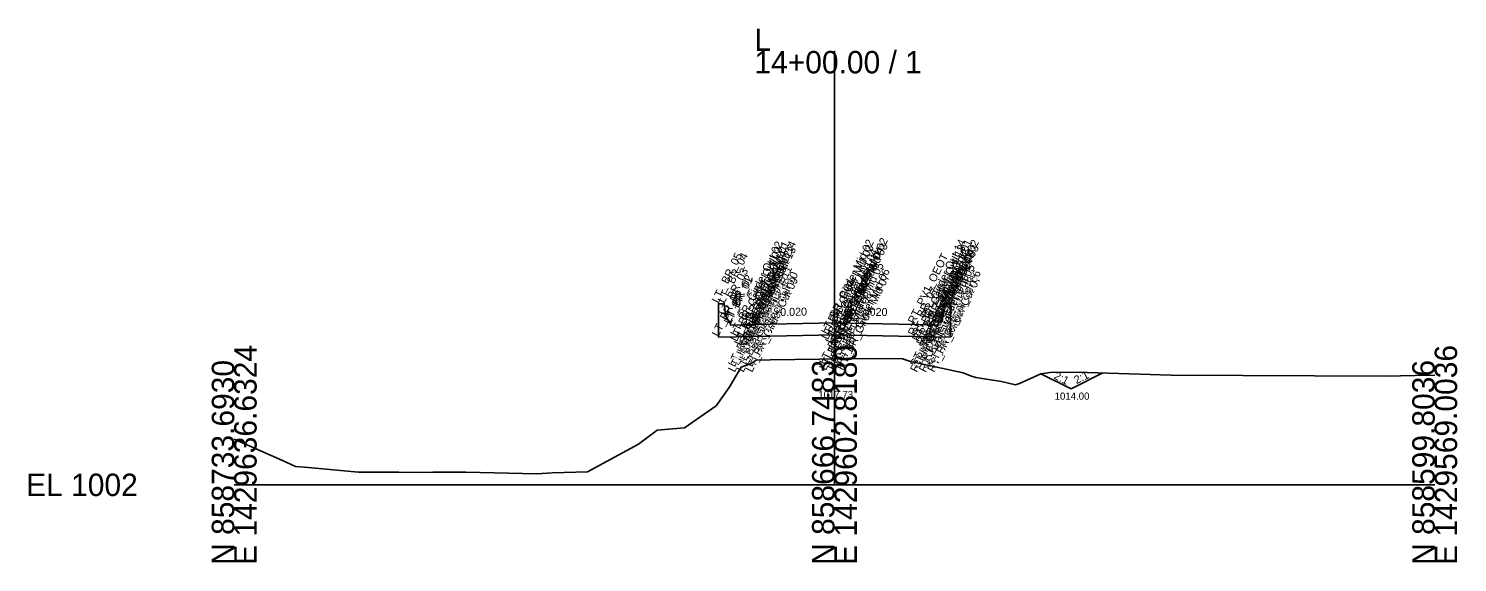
# Model space of a CAD drawing. Extents: x -26 to 153, y -10 to 13058.
# Drawn here: x -25.7 to 152.8, y 4990.3 to 5057 of the extents above; entities that cross this region are included whole.
import ezdxf

# ---------------------------------------------------------------- set-up
doc = ezdxf.new("R2010")
doc.units = 0
for name, color, linetype in [('Default', 7, 'Continuous'), ('Exist Cross Section Cell', 7, 'Continuous'), ('Exist XS Center Line Elevation Label', 7, 'Continuous'), ('Exist XS Ground Line', 7, 'Continuous'), ('Prop CMT Concrete Structures', 7, 'Continuous'), ('Prop CMT Slope Grass', 7, 'Continuous'), ('Prop XS Dump Level', 7, 'Continuous'), ('Prop XS SE Text', 7, 'Continuous'), ('Prop XS Side Slope Text', 7, 'Continuous')]:
    doc.layers.add(name, color=color, linetype=linetype)

msp = doc.modelspace()

# ---------------------------------------------------------------- linework, layer by layer
at = {"layer": 'Exist Cross Section Cell'}
for p, q in [((75, 5000), (75, 5054.22)), ((0, 5000), (75, 5000)), ((75, 5000), (150, 5000))]:
    msp.add_line(p, q, dxfattribs=at)
at = {"layer": 'Exist XS Ground Line'}
msp.add_lwpolyline([(0, 5005.73), (6.02, 5003.05), (7.64, 5002.3), (8.79, 5002.22), (15.53, 5001.6), (20.58, 5001.57), (23.13, 5001.56), (24.82, 5001.58), (28.93, 5001.59), (37.81, 5001.39), (39.72, 5001.51), (44.15, 5001.64), (50.51, 5005.07), (52.85, 5006.83), (56.25, 5007.14), (60.2, 5009.88), (61.83, 5012.15), (63.34, 5014.71), (64.6, 5015.17), (65.23, 5015.6), (66.95, 5015.62), (73.15, 5015.71), (75, 5015.73), (78.87, 5015.79), (83.49, 5015.75), (84.51, 5015.41), (91.07, 5013.99), (91.98, 5013.62), (92.66, 5013.43), (95.86, 5012.93), (97.63, 5012.48), (98.11, 5012.68), (100.8, 5013.88), (101.94, 5014.06), (105.28, 5014.08), (115.76, 5013.76), (117.06, 5013.69), (143.93, 5013.58), (147.53, 5013.65), (150, 5013.69)], dxfattribs=at)
at = {"layer": 'Prop CMT Concrete Structures'}
for points in [[(75, 5020.23), (65, 5020.03), (62, 5019.97), (61.99, 5020.22), (61.41, 5021.05), (61.24, 5022.63), (60.5, 5022.63), (60.5, 5018.44)], [(75, 5020.23), (85, 5020.03), (88, 5019.97), (88.01, 5020.22), (88.59, 5021.05), (88.76, 5022.63), (89.5, 5022.63), (89.5, 5018.44)], [(60.5, 5018.44), (65, 5018.53), (75, 5018.73)], [(75, 5018.73), (75, 5020.23)], [(75, 5018.73), (75, 5020.23)], [(89.5, 5018.44), (85, 5018.53), (75, 5018.73)]]:
    msp.add_lwpolyline(points, dxfattribs=at)
at = {"layer": 'Prop CMT Slope Grass'}
for q in [(100.8, 5013.88), (108.52, 5013.98)]:
    msp.add_line((104.56, 5012), q, dxfattribs=at)

# ---------------------------------------------------------------- texts
at = {"layer": 'Default'}
for s, height, p in [('1014.00', 0.9, (102.51, 5010.64)), ('-', 0.0001, (0, 5000))]:
    msp.add_text(s, height=height, dxfattribs=at).set_placement(p)
at = {"layer": 'Exist Cross Section Cell'}
for s, p in [('L', (65, 5054.22)), ('14+00.00 / 1', (65, 5051.42)), ('EL 1002', (-26, 4998.6))]:
    msp.add_text(s, height=2.8, dxfattribs=at).set_placement(p)
for s, p in [('E 1429636.6324', (2.8, 4990)), ('E 1429602.8180', (77.8, 4990)), ('E 1429569.0036', (152.8, 4990)), ('N 858733.6930', (0, 4990)), ('N 858666.7483', (75, 4990)), ('N 858599.8036', (150, 4990))]:
    msp.add_text(s, height=2.8, rotation=90, dxfattribs=at).set_placement(p)
at = {"layer": 'Exist XS Center Line Elevation Label'}
msp.add_text('1017.73', height=0.9, dxfattribs=at).set_placement((72.98, 5010.83))
msp.add_text('1017.73', height=0.9, dxfattribs=at).set_placement((72.98, 5010.83))
msp.add_text('1017.73', height=0.9, dxfattribs=at).set_placement((72.98, 5010.83))
at = {"layer": 'Prop XS Dump Level'}
for s, p in [('LT_BR_Girder Out 02', (62.79, 5018.48)), ('LT_BR_Girder Out 03', (62.79, 5017.83)), ('LT_BR_Girder Out 04', (63.29, 5017.33)), ('LT_BR_Girder Out 01', (63.62, 5018.5)), ('LT_BR_Girder Out 12', (63.96, 5017.33)), ('LT_BR_Girder Out 14', (64.46, 5018.52)), ('LT_BR_Girder Out 13', (64.46, 5017.83)), ('LT_BR_Girder Mid 02', (74.17, 5018.71)), ('LT_BR_Girder Mid 03', (74.17, 5018.06)), ('LT_BR_Girder Mid 04', (74.67, 5017.56)), ('RT_BR_Girder Mid 04', (75.33, 5017.56)), ('RT_BR_Girder Mid 02', (75.83, 5018.71)), ('RT_BR_Girder Mid 03', (75.83, 5018.06)), ('RT_BR_Girder Out 14', (85.54, 5018.52)), ('RT_BR_Girder Out 13', (85.54, 5017.83)), ('RT_BR_Girder Out 12', (86.04, 5017.33)), ('RT_BR_Girder Out 01', (86.38, 5018.5)), ('RT_BR_Girder Out 04', (86.71, 5017.33)), ('RT_BR_Girder Out 02', (87.21, 5018.48)), ('RT_BR_Girder Out 03', (87.21, 5017.83)), ('LT_ BR_05', (60.5, 5022.63)), ('LT_ BR_04', (61.24, 5022.63)), ('LT_PV1_OEOT', (65, 5020.03)), ('LT_BR_Girder Mid 05', (74.67, 5015.64)), ('RT_BR_Girder Mid 05', (75.33, 5015.64)), ('RT_PV1_OEOT', (85, 5020.03)), ('RT_BR_Girder Out 05', (86.71, 5015.42)), ('RT_ BR_04', (88.76, 5022.63)), ('RT_ BR_05', (89.5, 5022.63)), ('LT_BR_03', (61.41, 5021.05)), ('LT_BR_02', (61.99, 5020.22)), ('LT_BR_01', (62, 5019.97)), ('LT_BR_Girder Out 06', (62.54, 5014.67)), ('LT_BR_Girder Out 07', (62.54, 5014)), ('LT_BR_Girder Out 05', (63.29, 5015.42)), ('LT_BR_Girder Out 08', (63.62, 5014)), ('LT_BR_Girder Out 11', (63.96, 5015.42)), ('LT_BR_Girder Out 10', (64.71, 5014.67)), ('LT_BR_Girder Out 09', (64.71, 5014)), ('LT_BR_Girder Mid 06', (73.92, 5014.89)), ('LT_BR_Girder Mid 07', (73.92, 5014.23)), ('RT_BR_Girder Mid 06', (76.08, 5014.89)), ('RT_BR_Girder Mid 07', (76.08, 5014.23)), ('RT_BR_Girder Out 10', (85.29, 5014.67)), ('RT_BR_Girder Out 09', (85.29, 5014)), ('RT_BR_Girder Out 11', (86.04, 5015.42)), ('RT_BR_Girder Out 08', (86.38, 5014)), ('RT_BR_Girder Out 06', (87.46, 5014.67)), ('RT_BR_Girder Out 07', (87.46, 5014)), ('RT_BR_01', (88, 5019.97)), ('RT_BR_02', (88.01, 5020.22)), ('RT_BR_03', (88.59, 5021.05)), ('LT_BR_06', (60.5, 5018.44)), ('LT_BR_07', (65, 5018.53)), ('PV1_PGL', (75, 5020.23)), ('BR_Girder Mid 08', (75, 5014.23)), ('RT_BR_07', (85, 5018.53)), ('RT_BR_06', (89.5, 5018.44)), ('BR_PGL', (75, 5018.73))]:
    msp.add_text(s, height=1, rotation=63.5833, dxfattribs=at).set_placement(p)
at = {"layer": 'Prop XS SE Text'}
for rotation, p in [(1.1458, (68.23, 5021.09)), (358.8542, (78.27, 5021.16))]:
    msp.add_text('0.020', height=1, rotation=rotation, dxfattribs=at).set_placement(p)
at = {"layer": 'Prop XS Side Slope Text'}
for rotation, p in [(333.4349, (102.33, 5013.31)), (26.5651, (105.24, 5012.58))]:
    msp.add_text('2:1', height=1, rotation=rotation, dxfattribs=at).set_placement(p)

doc.saveas('drawing.dxf')
